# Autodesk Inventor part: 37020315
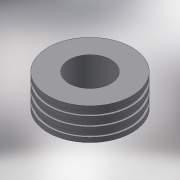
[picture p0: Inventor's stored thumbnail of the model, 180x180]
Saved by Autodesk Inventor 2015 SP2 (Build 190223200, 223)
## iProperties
Created: 2017-08
Part Number: 37020315
Material: Generic
Description: PLASSON MAN HOLE ADAPTOR 315
Document SubType Name: Modeling
Designer: Кирилл
Density: 1 g/cm^3
Appearance: Default
Author: Кирилл
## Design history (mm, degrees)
derived "37020-477207.ipt"
feature "Solid1::37020-477207.ipt"
tag "TaggingFeature1"
body "Solid1"
other parameters: "d0" = 135, "d2" = 427.5, "d3" = 278, "d4" = 315, "d6" = 46, "L_" = 135, "d_" = 315, "d_1" = 278, "H_" = 46
